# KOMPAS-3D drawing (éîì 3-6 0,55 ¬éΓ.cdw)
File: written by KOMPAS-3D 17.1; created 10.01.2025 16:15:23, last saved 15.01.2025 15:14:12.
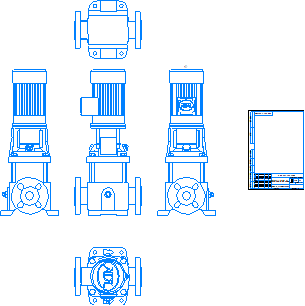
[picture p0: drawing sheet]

Sheet 1: A4, portrait

Title block, sheet 1: name: ВМН 3-6 0,55 кВт; designation: ВМН 3-6 0,55 кВт; material: Сталь 10  ГОСТ 1050-2013; mass: 67,15; sheets: 1; sheet format: A4; stored path: \\adlc.lan\data\АДЛ_ПКД\3D-модели\ADL production\Насосы ГРАНПАМП\Насосы ВМН\ВМН3\KOMPAS 3D\3-6 0,55 кВт _ ВМН.cdw

Views: Проекционный вид 2, Проекционный вид 3, Проекционный вид 4, Проекционный вид 5
Referenced files in \\adlc.lan\data\АДЛ_ПКД\3D-модели\ADL production\Насосы ГРАНПАМП\Насосы ВМН\ВМН3\KOMPAS 3D\: ВМН 3-6 0,55 кВт.m3d
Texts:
  Andrey
  АДЛ
Dimensions and other numbers on the sheet: 1:1; 1; 67,15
